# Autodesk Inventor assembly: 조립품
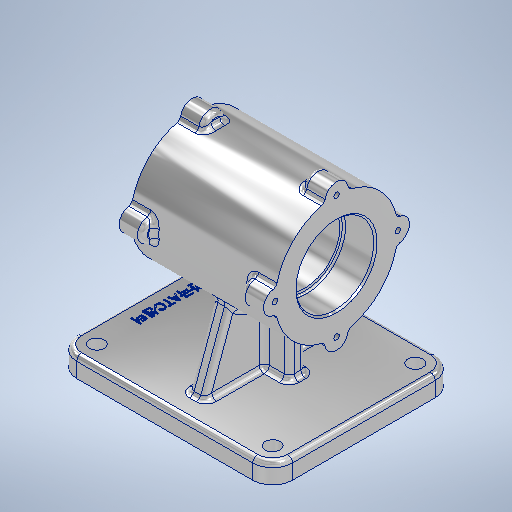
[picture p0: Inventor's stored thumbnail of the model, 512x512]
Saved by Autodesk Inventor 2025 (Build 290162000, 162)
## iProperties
Created: 2024-08
Part Number: 조립품
Document SubType Name: Assembly
Designer: 학생
Author: 학생
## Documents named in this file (12)
- C:\Users\학생\Desktop\740807V1003\조립품.iam
- C:\Users\학생\Desktop\740807V1003\본체.ipt
- C:\Users\학생\Desktop\740709V1005\Ű 4 x 4\Ű 4 x 4.ipt
- C:\Users\학생\Desktop\740709V1005\V-벨트풀리\V-벨트풀리.ipt
- C:\Users\학생\Desktop\740709V1005\개스킷\개스킷.ipt
- C:\Users\학생\Desktop\740709V1005\너트 M12 x 1.25\너트 M12 x 1.25.ipt
- C:\Users\학생\Desktop\740709V1005\뒤커버\뒤커버.ipt
- C:\Users\학생\Desktop\740709V1005\베어링 6204\베어링 6204.ipt
- C:\Users\학생\Desktop\740709V1005\볼트 M4 x 12\볼트 M4 x 12.ipt
- C:\Users\학생\Desktop\740709V1005\앞커버\앞커버.ipt
- C:\Users\학생\Desktop\740709V1005\오일실\오일실.ipt
- C:\Users\학생\Desktop\740709V1005\축\축.ipt
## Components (4 placed, 3 different names)
1. Ű 4 x 4:1 — 각도:1, 각도:2
2. V-벨트풀리:1 — 각도:2
3. 개스킷:1
4. 개스킷:2
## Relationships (2: Angle 2)
- 각도:1 [Angle]: Ű 4 x 4:1
- 각도:2 [Angle]: Ű 4 x 4:1 ↔ V-벨트풀리:1
